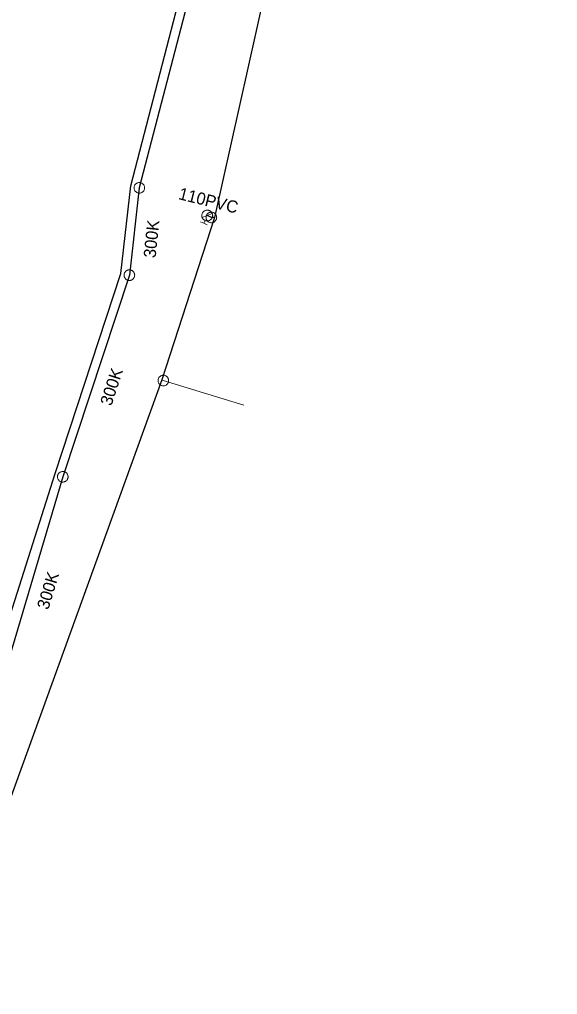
# Model space of a CAD drawing. Extents: x -741806 to -738704, y -1059275 to -1055387.
# Drawn here: x -740533.4 to -740489, y -1057880.2 to -1057799.9 of the extents above; entities that cross this region are included whole.
import ezdxf

# ---------------------------------------------------------------- set-up
doc = ezdxf.new("R2010")
doc.units = 0
doc.header["$LTSCALE"] = 0.4
for name, color, linetype, lineweight in [('2', 7, 'Continuous', 25), ('21', 7, 'Continuous', 13), ('3', 7, 'Continuous', 13), ('50', 7, 'Continuous', 13), ('51', 7, 'Continuous', 13), ('52', 7, 'Continuous', 25)]:
    doc.layers.add(name, color=color, linetype=linetype, lineweight=lineweight)
doc.layers.add('5', color=7, linetype='Continuous')
doc.layers.add('53', color=7, linetype='Continuous')

msp = doc.modelspace()

# ---------------------------------------------------------------- linework, layer by layer
at = {"layer": '2'}
for p, q in [((-740511.69, -1057768.149), (-740523.53, -1057813.78)), ((-740523.53, -1057813.78), (-740524.35, -1057820.98)), ((-740524.35, -1057820.98), (-740529.84, -1057837.59)), ((-740529.84, -1057837.59), (-740534.91, -1057854.649))]:
    msp.add_line(p, q, dxfattribs=at)
msp.add_lwpolyline([(-740609.006, -1057979.487), (-740608.671, -1057978.605), (-740585.671, -1057978.608), (-740567.046, -1057933.639), (-740552.184, -1057895.72), (-740535.835, -1057854.115), (-740530.462, -1057837.318), (-740525.059, -1057820.845), (-740524.232, -1057813.604), (-740512.355, -1057767.872), (-740507.212, -1057752.35), (-740500.784, -1057723.652), (-740491.688, -1057677.854), (-740489.039, -1057665.21)], dxfattribs=at)
at = {"layer": '21'}
msp.add_lwpolyline([(-740521.664, -1057829.6), (-740521.55, -1057829.659), (-740514.92, -1057831.686)], dxfattribs=at)
at = {"layer": '3'}
for points in [[(-740523.64, -1057814.203), (-740523.596, -1057814.212), (-740523.55, -1057814.216), (-740523.504, -1057814.216), (-740523.459, -1057814.211), (-740523.414, -1057814.201), (-740523.37, -1057814.187), (-740523.329, -1057814.167), (-740523.289, -1057814.145), (-740523.253, -1057814.117), (-740523.219, -1057814.086), (-740523.188, -1057814.052), (-740523.161, -1057814.015), (-740523.14, -1057813.975), (-740523.12, -1057813.933), (-740523.107, -1057813.889), (-740523.097, -1057813.844), (-740523.094, -1057813.799), (-740523.093, -1057813.753), (-740523.099, -1057813.707), (-740523.109, -1057813.662), (-740523.124, -1057813.619), (-740523.142, -1057813.578), (-740523.166, -1057813.538), (-740523.192, -1057813.501), (-740523.224, -1057813.467), (-740523.258, -1057813.438), (-740523.295, -1057813.411), (-740523.335, -1057813.388), (-740523.377, -1057813.37), (-740523.421, -1057813.356), (-740523.465, -1057813.347), (-740523.511, -1057813.342), (-740523.557, -1057813.343), (-740523.603, -1057813.348), (-740523.647, -1057813.358), (-740523.691, -1057813.372), (-740523.732, -1057813.391), (-740523.772, -1057813.415), (-740523.808, -1057813.442), (-740523.842, -1057813.472), (-740523.872, -1057813.507), (-740523.9, -1057813.544), (-740523.922, -1057813.584), (-740523.94, -1057813.625), (-740523.954, -1057813.669), (-740523.964, -1057813.714), (-740523.968, -1057813.76), (-740523.968, -1057813.805), (-740523.962, -1057813.851), (-740523.952, -1057813.896), (-740523.937, -1057813.939), (-740523.919, -1057813.981), (-740523.895, -1057814.02), (-740523.869, -1057814.057), (-740523.837, -1057814.091), (-740523.803, -1057814.122), (-740523.766, -1057814.148), (-740523.726, -1057814.171), (-740523.684, -1057814.189), (-740523.641, -1057814.203)], [(-740524.4, -1057821.415), (-740524.355, -1057821.417), (-740524.309, -1057821.415), (-740524.263, -1057821.408), (-740524.219, -1057821.397), (-740524.176, -1057821.381), (-740524.135, -1057821.36), (-740524.097, -1057821.335), (-740524.06, -1057821.307), (-740524.028, -1057821.275), (-740523.999, -1057821.24), (-740523.974, -1057821.201), (-740523.952, -1057821.161), (-740523.936, -1057821.118), (-740523.923, -1057821.074), (-740523.916, -1057821.029), (-740523.913, -1057820.983), (-740523.915, -1057820.937), (-740523.921, -1057820.892), (-740523.933, -1057820.848), (-740523.95, -1057820.805), (-740523.97, -1057820.764), (-740523.994, -1057820.726), (-740524.023, -1057820.69), (-740524.055, -1057820.657), (-740524.091, -1057820.628), (-740524.129, -1057820.603), (-740524.169, -1057820.581), (-740524.212, -1057820.564), (-740524.256, -1057820.552), (-740524.302, -1057820.545), (-740524.346, -1057820.542), (-740524.392, -1057820.544), (-740524.438, -1057820.551), (-740524.483, -1057820.563), (-740524.525, -1057820.578), (-740524.566, -1057820.599), (-740524.604, -1057820.623), (-740524.641, -1057820.652), (-740524.673, -1057820.684), (-740524.702, -1057820.719), (-740524.727, -1057820.757), (-740524.749, -1057820.798), (-740524.766, -1057820.84), (-740524.778, -1057820.884), (-740524.785, -1057820.93), (-740524.788, -1057820.976), (-740524.787, -1057821.021), (-740524.78, -1057821.066), (-740524.768, -1057821.111), (-740524.751, -1057821.154), (-740524.731, -1057821.195), (-740524.707, -1057821.234), (-740524.678, -1057821.269), (-740524.646, -1057821.302), (-740524.61, -1057821.331), (-740524.572, -1057821.357), (-740524.532, -1057821.377), (-740524.489, -1057821.394), (-740524.445, -1057821.406), (-740524.401, -1057821.415)], [(-740529.977, -1057838.005), (-740529.934, -1057838.016), (-740529.889, -1057838.024), (-740529.842, -1057838.027), (-740529.797, -1057838.025), (-740529.752, -1057838.018), (-740529.707, -1057838.006), (-740529.665, -1057837.99), (-740529.623, -1057837.97), (-740529.585, -1057837.944), (-740529.55, -1057837.916), (-740529.517, -1057837.884), (-740529.487, -1057837.848), (-740529.463, -1057837.81), (-740529.441, -1057837.77), (-740529.425, -1057837.726), (-740529.413, -1057837.682), (-740529.406, -1057837.637), (-740529.403, -1057837.592), (-740529.405, -1057837.546), (-740529.412, -1057837.5), (-740529.424, -1057837.456), (-740529.44, -1057837.414), (-740529.461, -1057837.372), (-740529.485, -1057837.334), (-740529.514, -1057837.298), (-740529.547, -1057837.266), (-740529.581, -1057837.237), (-740529.62, -1057837.211), (-740529.661, -1057837.19), (-740529.704, -1057837.174), (-740529.747, -1057837.162), (-740529.792, -1057837.154), (-740529.839, -1057837.152), (-740529.885, -1057837.154), (-740529.929, -1057837.161), (-740529.974, -1057837.172), (-740530.016, -1057837.189), (-740530.058, -1057837.21), (-740530.095, -1057837.234), (-740530.131, -1057837.262), (-740530.164, -1057837.295), (-740530.194, -1057837.33), (-740530.219, -1057837.368), (-740530.24, -1057837.409), (-740530.256, -1057837.452), (-740530.268, -1057837.496), (-740530.276, -1057837.541), (-740530.278, -1057837.587), (-740530.276, -1057837.633), (-740530.269, -1057837.678), (-740530.257, -1057837.722), (-740530.241, -1057837.765), (-740530.22, -1057837.806), (-740530.196, -1057837.844), (-740530.167, -1057837.88), (-740530.135, -1057837.913), (-740530.1, -1057837.942), (-740530.061, -1057837.967), (-740530.02, -1057837.988), (-740529.978, -1057838.005)]]:
    msp.add_lwpolyline(points, dxfattribs=at)
at = {"layer": '50'}
for p, q in [((-740517.928, -1057816.065), (-740518.341, -1057816.225)), ((-740517.928, -1057816.065), (-740517.51, -1057815.902)), ((-740518.488, -1057816.582), (-740518.207, -1057816.705)), ((-740518.106, -1057816.475), (-740518.207, -1057816.705)), ((-740517.925, -1057816.829), (-740518.207, -1057816.705))]:
    msp.add_line(p, q, dxfattribs=at)
msp.add_lwpolyline([(-740518.333, -1057815.883), (-740518.35, -1057815.929), (-740518.364, -1057815.974), (-740518.37, -1057816.021), (-740518.372, -1057816.067), (-740518.37, -1057816.111), (-740518.362, -1057816.16), (-740518.35, -1057816.204), (-740518.334, -1057816.249), (-740518.314, -1057816.29), (-740518.287, -1057816.328), (-740518.258, -1057816.365), (-740518.226, -1057816.4), (-740518.188, -1057816.427), (-740518.149, -1057816.453), (-740518.108, -1057816.474), (-740518.065, -1057816.49), (-740518.022, -1057816.504), (-740517.974, -1057816.51), (-740517.927, -1057816.512), (-740517.879, -1057816.51), (-740517.834, -1057816.503), (-740517.789, -1057816.491), (-740517.745, -1057816.474), (-740517.705, -1057816.454), (-740517.664, -1057816.428), (-740517.627, -1057816.399), (-740517.596, -1057816.366), (-740517.564, -1057816.33), (-740517.541, -1057816.29), (-740517.517, -1057816.25), (-740517.501, -1057816.205), (-740517.49, -1057816.159), (-740517.482, -1057816.115), (-740517.478, -1057816.067), (-740517.482, -1057816.021), (-740517.488, -1057815.974), (-740517.501, -1057815.93), (-740517.517, -1057815.885), (-740517.539, -1057815.843), (-740517.565, -1057815.805), (-740517.595, -1057815.768), (-740517.628, -1057815.736), (-740517.662, -1057815.706), (-740517.704, -1057815.679), (-740517.744, -1057815.658), (-740517.788, -1057815.642), (-740517.833, -1057815.631), (-740517.88, -1057815.622), (-740517.926, -1057815.62), (-740517.974, -1057815.623), (-740518.018, -1057815.629), (-740518.065, -1057815.642), (-740518.107, -1057815.658), (-740518.149, -1057815.678), (-740518.187, -1057815.706), (-740518.225, -1057815.733), (-740518.258, -1057815.766), (-740518.286, -1057815.804), (-740518.311, -1057815.842)], close=True, dxfattribs=at)
at = {"layer": '51'}
for points in [[(-740518.024, -1057816.217), (-740518.023, -1057816.262), (-740518.016, -1057816.307), (-740518.004, -1057816.352), (-740517.988, -1057816.394), (-740517.967, -1057816.436), (-740517.942, -1057816.475), (-740517.914, -1057816.51), (-740517.882, -1057816.543), (-740517.846, -1057816.571), (-740517.808, -1057816.596), (-740517.767, -1057816.617), (-740517.724, -1057816.634), (-740517.68, -1057816.647), (-740517.635, -1057816.654), (-740517.589, -1057816.656), (-740517.543, -1057816.654), (-740517.498, -1057816.647), (-740517.454, -1057816.636), (-740517.411, -1057816.619), (-740517.37, -1057816.598), (-740517.332, -1057816.573), (-740517.296, -1057816.545), (-740517.264, -1057816.512), (-740517.234, -1057816.477), (-740517.209, -1057816.438), (-740517.188, -1057816.398), (-740517.172, -1057816.356), (-740517.16, -1057816.311), (-740517.153, -1057816.266), (-740517.149, -1057816.22), (-740517.152, -1057816.175), (-740517.159, -1057816.13), (-740517.171, -1057816.085), (-740517.187, -1057816.043), (-740517.208, -1057816.001), (-740517.233, -1057815.962), (-740517.261, -1057815.927), (-740517.293, -1057815.894), (-740517.329, -1057815.866), (-740517.367, -1057815.841), (-740517.408, -1057815.82), (-740517.451, -1057815.803), (-740517.495, -1057815.791), (-740517.54, -1057815.783), (-740517.586, -1057815.781), (-740517.632, -1057815.783), (-740517.677, -1057815.791), (-740517.721, -1057815.801), (-740517.764, -1057815.818), (-740517.805, -1057815.839), (-740517.843, -1057815.864), (-740517.879, -1057815.892), (-740517.911, -1057815.925), (-740517.941, -1057815.96), (-740517.966, -1057815.999), (-740517.987, -1057816.039), (-740518.003, -1057816.081), (-740518.015, -1057816.126), (-740518.022, -1057816.171), (-740518.024, -1057816.216)], [(-740521.162, -1057829.861), (-740521.143, -1057829.82), (-740521.129, -1057829.777), (-740521.118, -1057829.732), (-740521.113, -1057829.687), (-740521.113, -1057829.641), (-740521.117, -1057829.595), (-740521.127, -1057829.55), (-740521.14, -1057829.506), (-740521.159, -1057829.465), (-740521.181, -1057829.425), (-740521.207, -1057829.388), (-740521.238, -1057829.353), (-740521.271, -1057829.322), (-740521.308, -1057829.295), (-740521.348, -1057829.272), (-740521.389, -1057829.252), (-740521.432, -1057829.237), (-740521.477, -1057829.228), (-740521.523, -1057829.223), (-740521.569, -1057829.223), (-740521.614, -1057829.227), (-740521.659, -1057829.235), (-740521.703, -1057829.25), (-740521.745, -1057829.267), (-740521.785, -1057829.29), (-740521.822, -1057829.317), (-740521.856, -1057829.347), (-740521.888, -1057829.381), (-740521.915, -1057829.418), (-740521.939, -1057829.457), (-740521.957, -1057829.499), (-740521.971, -1057829.542), (-740521.981, -1057829.587), (-740521.987, -1057829.632), (-740521.987, -1057829.678), (-740521.983, -1057829.724), (-740521.973, -1057829.768), (-740521.96, -1057829.812), (-740521.941, -1057829.854), (-740521.919, -1057829.894), (-740521.893, -1057829.931), (-740521.862, -1057829.966), (-740521.828, -1057829.996), (-740521.792, -1057830.024), (-740521.752, -1057830.047), (-740521.711, -1057830.067), (-740521.667, -1057830.08), (-740521.623, -1057830.091), (-740521.577, -1057830.096), (-740521.531, -1057830.096), (-740521.486, -1057830.092), (-740521.441, -1057830.084), (-740521.397, -1057830.069), (-740521.355, -1057830.051), (-740521.315, -1057830.028), (-740521.277, -1057830.002), (-740521.244, -1057829.972), (-740521.212, -1057829.938), (-740521.185, -1057829.901), (-740521.163, -1057829.862)]]:
    msp.add_lwpolyline(points, dxfattribs=at)
at = {"layer": '52'}
for points in [[(-740489.868, -1057679.99), (-740497.519, -1057704.287), (-740502.89, -1057727.946), (-740504.09, -1057731.52), (-740504.16, -1057731.78), (-740504.295, -1057732.394), (-740505.458, -1057737.884), (-740512.487, -1057766.415), (-740507.033, -1057770.061), (-740517.328, -1057816.22), (-740521.664, -1057829.6), (-740544.85, -1057893.509), (-740554.399, -1057919.446), (-740570.451, -1057950.712), (-740592.697, -1058007.398), (-740600.714, -1058010.487), (-740613.05, -1058039.97), (-740626.485, -1058069.3)], [(-740517.328, -1057816.22), (-740517.588, -1057816.22), (-740517.93, -1057816.07)]]:
    msp.add_lwpolyline(points, dxfattribs=at)

# ---------------------------------------------------------------- texts
at = {"layer": '5'}
for rotation, p in [(84, (-740522.193, -1057819.591)), (72, (-740525.836, -1057831.806)), (73, (-740531.041, -1057848.602))]:
    msp.add_text('300K', height=1, rotation=rotation, dxfattribs=at).set_placement(p)
at = {"layer": '53'}
msp.add_text('110PVC', height=1, rotation=346, dxfattribs=at).set_placement((-740520.359, -1057814.702))

doc.saveas('drawing.dxf')
